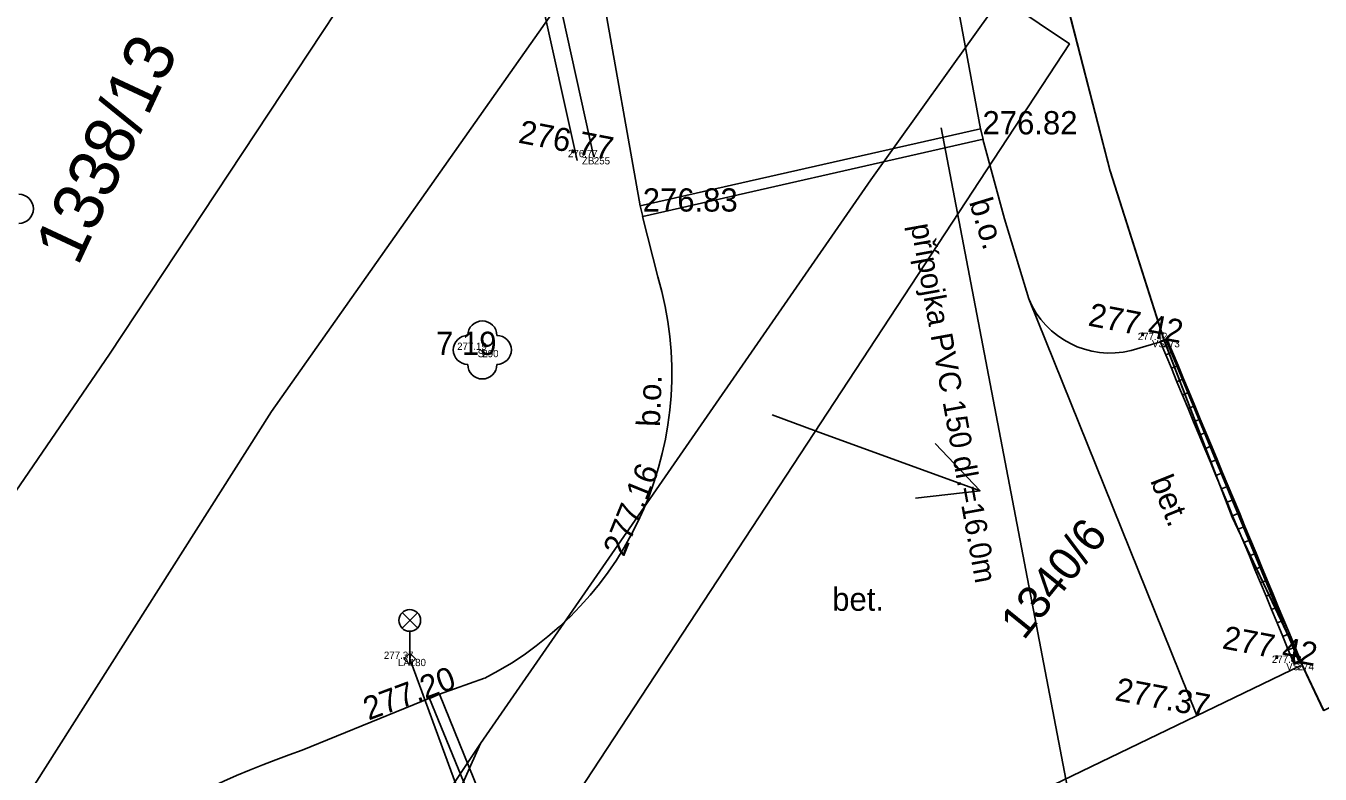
# Model space of a CAD drawing. Extents: x -601602 to -600882, y -1162594 to -1161950.
# Drawn here: x -601230.67 to -601208.38, y -1162065.09 to -1162052.2 of the extents above; entities that cross this region are included whole.
import ezdxf

# ---------------------------------------------------------------- set-up
doc = ezdxf.new("R2010")
doc.units = 0
for name, color, linetype in [('BODY', 7, 'Continuous'), ('BODY_CISLA', 7, 'Continuous'), ('BODY_KODY', 7, 'Continuous'), ('BODY_VYSKY_CELE', 7, 'Continuous'), ('G_ZELEN', 7, 'Continuous'), ('G_ZNACKY', 7, 'Continuous'), ('H_KOTY_VYSKOVE', 7, 'Continuous'), ('H_VYSKY_PREVZATE', 7, 'Continuous'), ('IS_KAN_SPLASKOVA', 7, 'Continuous'), ('IS_VO_AREAL', 7, 'Continuous'), ('KN_Hranice parcel', 7, 'Continuous'), ('KN_Parcelní čísla', 7, 'Continuous'), ('KN_Pop  PČ popisy', 7, 'Continuous'), ('Vrstva 7', 7, 'Continuous')]:
    doc.layers.add(name, color=color, linetype=linetype)

# ---------------------------------------------------------------- blocks, each defined once
blk = doc.blocks.new('POINT_DISPLAY')
blk.add_line((0, 0), (0, 0))
blk = doc.blocks.new('1029_52')
at = {"layer": 'KN_Pop  PČ popisy'}
for p, q in [((0, 0), (2.82, -1.026)), ((2.82, -1.026), (2.05, -0.213)), ((2.82, -1.026), (1.708, -1.154))]:
    blk.add_line(p, q, dxfattribs=at)

msp = doc.modelspace()

# ---------------------------------------------------------------- linework, layer by layer
at = {"layer": 'G_ZELEN'}
msp.add_circle((-601222.81, -1162057.78), 0.00025, dxfattribs=at)
for centre, start, end in [((-601230.79, -1162055.35), 270, 90), ((-601222.81, -1162057.53), 0, 180), ((-601223.06, -1162057.78), 90, 270), ((-601222.56, -1162057.78), 270, 90), ((-601222.81, -1162058.03), 180, 360)]:
    msp.add_arc(centre, 0.25, start, end, dxfattribs=at)
at = {"layer": 'G_ZNACKY'}
for p, q in [((-601224.192, -1162062.569), (-601223.928, -1162062.305)), ((-601223.924, -1162062.567), (-601224.188, -1162062.303)), ((-601224.06, -1162062.625), (-601224.06, -1162063))]:
    msp.add_line(p, q, dxfattribs=at)
for points in [[(-601224.06, -1162063.2), (-601224.16, -1162063.1), (-601224.06, -1162063)], [(-601224.06, -1162063.2), (-601224.06, -1162063), (-601223.96, -1162063.1)]]:
    msp.add_lwpolyline(points, close=True, dxfattribs=at)
msp.add_circle((-601224.06, -1162062.438), 0.188, dxfattribs=at)
at = {"layer": 'IS_KAN_SPLASKOVA'}
msp.add_line((-601214.91, -1162053.957), (-601211.895, -1162069.701), dxfattribs=at)
at = {"layer": 'IS_VO_AREAL'}
msp.add_lwpolyline([(-601221, -1162071.19), (-601221.34, -1162070.51), (-601224.06, -1162063.1)], dxfattribs=at)
at = {"layer": 'KN_Hranice parcel'}
for p, q in [((-601216.12, -1162054.85), (-601222.84, -1162064.56)), ((-601222.84, -1162064.56), (-601226.88, -1162070.6))]:
    msp.add_line(p, q, dxfattribs=at)
for points in [[(-601189.34, -1162032.73), (-601190.11, -1162036.89), (-601190.25, -1162040.9), (-601189.75, -1162045.18), (-601189.25, -1162047.73), (-601188.26, -1162050.73), (-601187.02, -1162053.44), (-601208.32, -1162063.99), (-601209.9, -1162060.66), (-601211.08, -1162057.59), (-601212, -1162054.7), (-601212.73, -1162051.88), (-601213.33, -1162048.91), (-601213.84, -1162044.87), (-601214.04, -1162041.62), (-601214.04, -1162038.88), (-601213.85, -1162035.48), (-601213.49, -1162032.3)], [(-601221.67, -1162046.41), (-601229.23, -1162057.85), (-601232.4, -1162062.48), (-601235.5, -1162068.38), (-601235.8, -1162069.05), (-601236.91, -1162071.54), (-601237.28, -1162072.25), (-601237.73, -1162072.9), (-601238.31, -1162073.49), (-601238.42, -1162073.58), (-601238.93, -1162074), (-601239.44, -1162074.3), (-601240.59, -1162074.86)], [(-601238.93, -1162085.03), (-601237.95, -1162082.12), (-601235.72, -1162076.14), (-601233.56, -1162071.26), (-601230.52, -1162065.27), (-601226.44, -1162058.84), (-601219, -1162048.28)], [(-601219, -1162048.28), (-601212.7, -1162052.51), (-601223.76, -1162069.37)], [(-601219, -1162048.28), (-601213.97, -1162051.84), (-601216.12, -1162054.85)], [(-601223.76, -1162069.37), (-601223.97, -1162068.96), (-601223.92, -1162066.98), (-601222.84, -1162064.56)]]:
    msp.add_lwpolyline(points, dxfattribs=at)
at = {"layer": 'KN_Pop  PČ popisy'}
msp.add_line((-601217.82, -1162058.9), (-601217.06, -1162059.18), dxfattribs=at)
at = {"layer": 'Vrstva 7'}
for p, q in [((-601221.584, -1162046.873), (-601220.09, -1162055.3)), ((-601215.176, -1162048.865), (-601214.23, -1162053.97)), ((-601221.18, -1162054.52), (-601221.9, -1162051.25)), ((-601220.89, -1162054.46), (-601221.61, -1162051.19)), ((-601212.725, -1162051.88), (-601212.002, -1162054.698)), ((-601214.23, -1162053.97), (-601220.09, -1162055.3)), ((-601214.189, -1162054.15), (-601214.23, -1162053.97)), ((-601214.23, -1162053.97), (-601214.23, -1162053.97)), ((-601220.049, -1162055.48), (-601214.189, -1162054.15)), ((-601213.82, -1162055.52), (-601214.19, -1162054.15)), ((-601212.002, -1162054.698), (-601211.077, -1162057.594)), ((-601220.09, -1162055.3), (-601220.049, -1162055.48)), ((-601220.05, -1162055.48), (-601219.79, -1162056.52)), ((-601213.4, -1162056.9), (-601213.82, -1162055.52)), ((-601213.4, -1162056.9), (-601210.506, -1162064.077)), ((-601211.033, -1162057.612), (-601211.64, -1162057.79)), ((-601211.077, -1162057.594), (-601209.898, -1162060.661)), ((-601208.74, -1162063.17), (-601211.033, -1162057.612)), ((-601209.898, -1162060.661), (-601208.324, -1162063.987)), ((-601214.66, -1162066.08), (-601208.718, -1162063.216)), ((-601222.77, -1162063.43), (-601223.55, -1162063.71)), ((-601225.91, -1162064.67), (-601223.55, -1162063.71)), ((-601223.72, -1162063.78), (-601223.55, -1162063.71)), ((-601221.45, -1162069.33), (-601223.72, -1162063.78)), ((-601223.55, -1162063.71), (-601221.28, -1162069.26)), ((-601223.55, -1162063.71), (-601223.55, -1162063.71))]:
    msp.add_line(p, q, dxfattribs=at)
for points in [[(-601211.022, -1162057.586), (-601210.926, -1162057.817), (-601211.042, -1162057.865), (-601211.138, -1162057.634)], [(-601210.926, -1162057.817), (-601210.83, -1162058.048), (-601210.946, -1162058.096), (-601211.042, -1162057.865)], [(-601210.83, -1162058.048), (-601210.735, -1162058.279), (-601210.85, -1162058.327), (-601210.946, -1162058.096)], [(-601210.735, -1162058.279), (-601210.639, -1162058.509), (-601210.754, -1162058.557), (-601210.85, -1162058.327)], [(-601210.639, -1162058.509), (-601210.543, -1162058.74), (-601210.658, -1162058.788), (-601210.754, -1162058.557)], [(-601210.543, -1162058.74), (-601210.447, -1162058.971), (-601210.562, -1162059.019), (-601210.658, -1162058.788)], [(-601210.447, -1162058.971), (-601210.351, -1162059.202), (-601210.466, -1162059.25), (-601210.562, -1162059.019)], [(-601210.351, -1162059.202), (-601210.255, -1162059.433), (-601210.37, -1162059.481), (-601210.466, -1162059.25)], [(-601210.255, -1162059.433), (-601210.159, -1162059.664), (-601210.274, -1162059.712), (-601210.37, -1162059.481)], [(-601210.159, -1162059.664), (-601210.063, -1162059.895), (-601210.179, -1162059.943), (-601210.274, -1162059.712)], [(-601210.063, -1162059.895), (-601209.967, -1162060.126), (-601210.083, -1162060.174), (-601210.179, -1162059.943)], [(-601209.967, -1162060.126), (-601209.871, -1162060.356), (-601209.987, -1162060.404), (-601210.083, -1162060.174)], [(-601209.871, -1162060.356), (-601209.775, -1162060.587), (-601209.891, -1162060.635), (-601209.987, -1162060.404)], [(-601209.775, -1162060.587), (-601209.679, -1162060.818), (-601209.795, -1162060.866), (-601209.891, -1162060.635)], [(-601209.679, -1162060.818), (-601209.584, -1162061.049), (-601209.699, -1162061.097), (-601209.795, -1162060.866)], [(-601209.584, -1162061.049), (-601209.488, -1162061.28), (-601209.603, -1162061.328), (-601209.699, -1162061.097)], [(-601209.488, -1162061.28), (-601209.392, -1162061.511), (-601209.507, -1162061.559), (-601209.603, -1162061.328)], [(-601209.392, -1162061.511), (-601209.296, -1162061.742), (-601209.411, -1162061.79), (-601209.507, -1162061.559)], [(-601209.296, -1162061.742), (-601209.2, -1162061.973), (-601209.315, -1162062.02), (-601209.411, -1162061.79)], [(-601209.2, -1162061.973), (-601209.104, -1162062.203), (-601209.219, -1162062.251), (-601209.315, -1162062.02)], [(-601209.104, -1162062.203), (-601209.008, -1162062.434), (-601209.123, -1162062.482), (-601209.219, -1162062.251)], [(-601209.008, -1162062.434), (-601208.912, -1162062.665), (-601209.028, -1162062.713), (-601209.123, -1162062.482)], [(-601208.912, -1162062.665), (-601208.816, -1162062.896), (-601208.932, -1162062.944), (-601209.028, -1162062.713)], [(-601208.816, -1162062.896), (-601208.72, -1162063.127), (-601208.836, -1162063.175), (-601208.932, -1162062.944)], [(-601208.72, -1162063.127), (-601208.712, -1162063.146), (-601208.828, -1162063.194), (-601208.836, -1162063.175)]]:
    msp.add_lwpolyline(points, close=True, dxfattribs=at)
for centre, radius, start, end in [((-601225.424, -1162058.188), 5.876, 296.8536, 16.4892), ((-601212.003, -1162056.322), 1.512, 202.4747, 283.8755), ((-601220.008, -1162081.444), 17.782, 109.3847, 134.3576)]:
    msp.add_arc(centre, radius, start, end, dxfattribs=at)

# ---------------------------------------------------------------- block references
at = {"layer": 'BODY'}
for p in [(-601220.89, -1162054.46), (-601222.81, -1162057.78), (-601211.08, -1162057.61), (-601224.06, -1162063.1), (-601208.77, -1162063.17)]:
    msp.add_blockref('POINT_DISPLAY', p, dxfattribs=at)
at = {"layer": 'KN_Pop  PČ popisy'}
msp.add_blockref('1029_52', (-601217.06, -1162059.18), dxfattribs=at)

# ---------------------------------------------------------------- texts
at = {"layer": 'BODY_CISLA'}
for s, p in [('255', (-601220.89, -1162054.585)), ('290', (-601222.81, -1162057.905)), ('273', (-601211.08, -1162057.735)), ('180', (-601224.06, -1162063.225)), ('274', (-601208.77, -1162063.295))]:
    msp.add_text(s, height=0.125, dxfattribs=at).set_placement(p)
at = {"layer": 'BODY_KODY'}
for s, p in [('ZB', (-601221.094, -1162054.585)), ('S', (-601222.891, -1162057.905)), ('VS', (-601211.279, -1162057.735)), ('LA', (-601224.264, -1162063.225)), ('VS', (-601208.969, -1162063.295))]:
    msp.add_text(s, height=0.125, dxfattribs=at).set_placement(p)
at = {"layer": 'BODY_VYSKY_CELE'}
for s, p in [('276.77 ', (-601221.335, -1162054.46)), ('277.42 ', (-601211.525, -1162057.61)), ('277.19 ', (-601223.244, -1162057.78)), ('277.37 ', (-601224.505, -1162063.1)), ('277.42 ', (-601209.215, -1162063.17))]:
    msp.add_text(s, height=0.125, dxfattribs=at).set_placement(p)
at = {"layer": 'H_KOTY_VYSKOVE'}
for s, p in [('276.77 ', (-601222.205, -1162054.208)), ('277.42 ', (-601212.395, -1162057.358)), ('277.42 ', (-601210.085, -1162062.918))]:
    msp.add_text(s, height=0.4, rotation=349.1372, dxfattribs=at).set_placement(p)
msp.add_text(' 7 19', height=0.4, dxfattribs=at).set_placement((-601223.756, -1162057.866))
at = {"layer": 'H_VYSKY_PREVZATE'}
for s, p in [('276.82', (-601214.198, -1162054.067)), ('276.83', (-601220.048, -1162055.397))]:
    msp.add_text(s, height=0.4, dxfattribs=at).set_placement(p)
for s, rotation, p in [('277.16 ', 67.9275, (-601220.374, -1162061.358)), ('277.20 ', 20.4445, (-601224.768, -1162064.164)), ('277.37 ', 349.3397, (-601211.934, -1162063.81))]:
    msp.add_text(s, height=0.4, rotation=rotation, dxfattribs=at).set_placement(p)
at = {"layer": 'IS_KAN_SPLASKOVA'}
msp.add_text('přípojka PVC 150 dl.=16.0m', height=0.375, rotation=280.2485, dxfattribs=at).set_placement((-601215.436, -1162055.631))
at = {"layer": 'KN_Parcelní čísla'}
for s, height, rotation, p in [('1338/13', 0.85, 65, (-601229.775, -1162056.354)), ('1340/6', 0.5695, 51, (-601213.489, -1162062.794))]:
    msp.add_text(s, height=height, rotation=rotation, dxfattribs=at).set_placement(p)
at = {"layer": 'Vrstva 7'}
for s, rotation, p in [('b.o.', 286.9275, (-601214.432, -1162055.23)), ('b.o.', 87.7286, (-601219.754, -1162059.109)), ('bet.', 291.9608, (-601211.314, -1162060.031))]:
    msp.add_text(s, height=0.4, rotation=rotation, dxfattribs=at).set_placement(p)
msp.add_text('bet.', height=0.4, dxfattribs=at).set_placement((-601216.786, -1162062.272))

doc.saveas('drawing.dxf')
